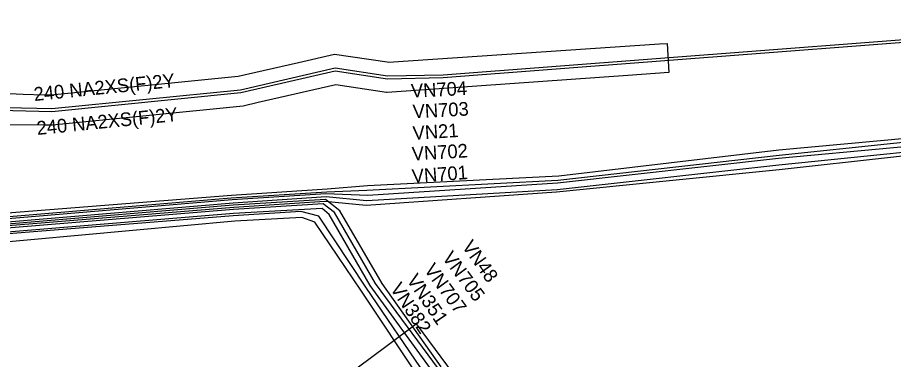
# Model space of a CAD drawing. Extents: x -545588 to -543214, y -1196037 to -1194452.
# Drawn here: x -545264.5 to -545200.6, y -1194915.7 to -1194890.7 of the extents above; entities that cross this region are included whole.
import ezdxf

# ---------------------------------------------------------------- set-up
doc = ezdxf.new("R2010")
doc.units = 0
for name, color, linetype in [('Vrstva 35', 7, 'Continuous'), ('Vrstva 5', 7, 'Continuous'), ('Vrstva 6', 7, 'Continuous'), ('Vrstva 7', 7, 'Continuous')]:
    doc.layers.add(name, color=color, linetype=linetype)

msp = doc.modelspace()

# ---------------------------------------------------------------- linework, layer by layer
at = {"layer": 'Vrstva 35'}
for points in [[(-545269.62, -1194896.02), (-545264.03, -1194896.28), (-545262.5, -1194896.33), (-545261.991, -1194896.349), (-545248.359, -1194894.982), (-545243.97, -1194893.97), (-545241.333, -1194893.361), (-545237.5, -1194893.94), (-545237.397, -1194893.959), (-545217.62, -1194892.62), (-545217.07, -1194892.58), (-545216.95, -1194894.72), (-545219.93, -1194894.93), (-545237.5, -1194896.16), (-545237.543, -1194896.161), (-545241.247, -1194895.599), (-545246.91, -1194896.91), (-545248.001, -1194897.158), (-545261.909, -1194898.551), (-545262.5, -1194898.55), (-545267.99, -1194898.54)], [(-545245.95, -1194920.95), (-545237.5, -1194914.64), (-545235.38, -1194913.06), (-545225.9, -1194925.9)]]:
    msp.add_lwpolyline(points, dxfattribs=at)
at = {"layer": 'Vrstva 5'}
for points in [[(-545268.613, -1194897.38), (-545261.946, -1194897.55), (-545248.164, -1194896.169), (-545241.286, -1194894.582), (-545237.477, -1194895.16), (-545233.395, -1194895.08), (-545178.862, -1194890.89)], [(-545268.587, -1194897.18), (-545261.954, -1194897.35), (-545248.196, -1194895.971), (-545241.294, -1194894.378), (-545237.463, -1194894.96), (-545233.405, -1194894.88), (-545178.878, -1194890.69)], [(-545192.21, -1194899.03), (-545208.9, -1194900.78), (-545225.05, -1194902.59), (-545238.97, -1194903.32), (-545241.89, -1194903.44), (-545248.86, -1194903.88), (-545267.1, -1194905.41)], [(-545192.24, -1194898.85), (-545208.93, -1194900.39), (-545224.97, -1194902.29), (-545238.93, -1194902.99), (-545241.87, -1194903.23), (-545248.84, -1194903.69), (-545267.05, -1194905.12)], [(-545192.21, -1194899.78), (-545208.91, -1194901.48), (-545225.09, -1194903.27), (-545239.01, -1194904.09), (-545241.95, -1194903.79), (-545248.73, -1194904.26), (-545267.223, -1194905.818)], [(-545192.17, -1194899.42), (-545208.95, -1194900.99), (-545225.07, -1194902.79), (-545238.89, -1194903.69), (-545241.97, -1194903.58), (-545248.8, -1194904.02), (-545267.18, -1194905.57)], [(-545192.22, -1194899.97), (-545208.89, -1194901.81), (-545225.13, -1194903.44), (-545239.03, -1194904.43), (-545242.04, -1194904.14), (-545248.68, -1194904.56), (-545267.25, -1194906.09)], [(-545233.75, -1194916.35), (-545238.35, -1194910.11), (-545241.34, -1194904.93), (-545242.16, -1194904.31), (-545248.71, -1194904.72), (-545267.29, -1194906.26)], [(-545233.55, -1194916.21), (-545237.86, -1194910.11), (-545240.94, -1194904.81), (-545241.99, -1194903.99), (-545248.73, -1194904.4), (-545267.223, -1194905.96)], [(-545234.13, -1194916.6), (-545238.74, -1194910.26), (-545241.72, -1194905.08), (-545242.22, -1194904.65), (-545248.71, -1194905.01), (-545267.267, -1194906.539)], [(-545234.65, -1194916.87), (-545239.05, -1194910.4), (-545242.48, -1194905.21), (-545243.78, -1194904.85), (-545248.72, -1194905.18), (-545267.26, -1194906.67)], [(-545235.07, -1194917.17), (-545239.41, -1194910.6), (-545242.76, -1194905.64), (-545243.71, -1194905.29), (-545248.61, -1194905.57), (-545267.22, -1194907.27)]]:
    msp.add_lwpolyline(points, dxfattribs=at)

# ---------------------------------------------------------------- texts
at = {"layer": 'Vrstva 6'}
for rotation, p in [(5.724, (-545263.219, -1194896.795)), (5.722, (-545263.008, -1194899.275))]:
    msp.add_text('240 NA2XS(F)2Y', height=1, rotation=rotation, dxfattribs=at).set_placement(p)
at = {"layer": 'Vrstva 7'}
for s, rotation, p in [('VN704', 2.871, (-545235.731, -1194896.551)), ('VN703', 3.002, (-545235.604, -1194898.061)), ('VN21', 3.726, (-545235.598, -1194899.634)), ('VN702', 3.371, (-545235.664, -1194901.144)), ('VN701', 4.074, (-545235.657, -1194902.78)), ('VN48', 305.243, (-545232.077, -1194907.414)), ('VN705', 306.397, (-545233.517, -1194908.24)), ('VN707', 306.022, (-545234.84, -1194909.118)), ('VN351', 304.218, (-545236.106, -1194909.86)), ('VN382', 303.448, (-545237.305, -1194910.484))]:
    msp.add_text(s, height=1, rotation=rotation, dxfattribs=at).set_placement(p)

doc.saveas('drawing.dxf')
